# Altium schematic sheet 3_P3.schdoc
size 307 x 218 mm; Symbol: Sheet-Symbol_A4; Device: Sheet-Symbol_A4; @Project Name: Project Name; @Page Count: 3; @Update Date: 2021.11.05; @Create Date: 2024-11-23; @Schematic Name: Schematic Name; @Page No: 1; @Page Name: P1; Company: EasyEDA.com; Version: V1.0; Page Size: A4; @Create Time: 4:43:57 PM; @Update Time: 1:48:45 AM; Title Block Position: 3; Width: 1170; Height: 825; Region Start: 1; X Region Count: 6; Y Region Count: 4; Blade Width: 10; @Board Name: PENTASLAM
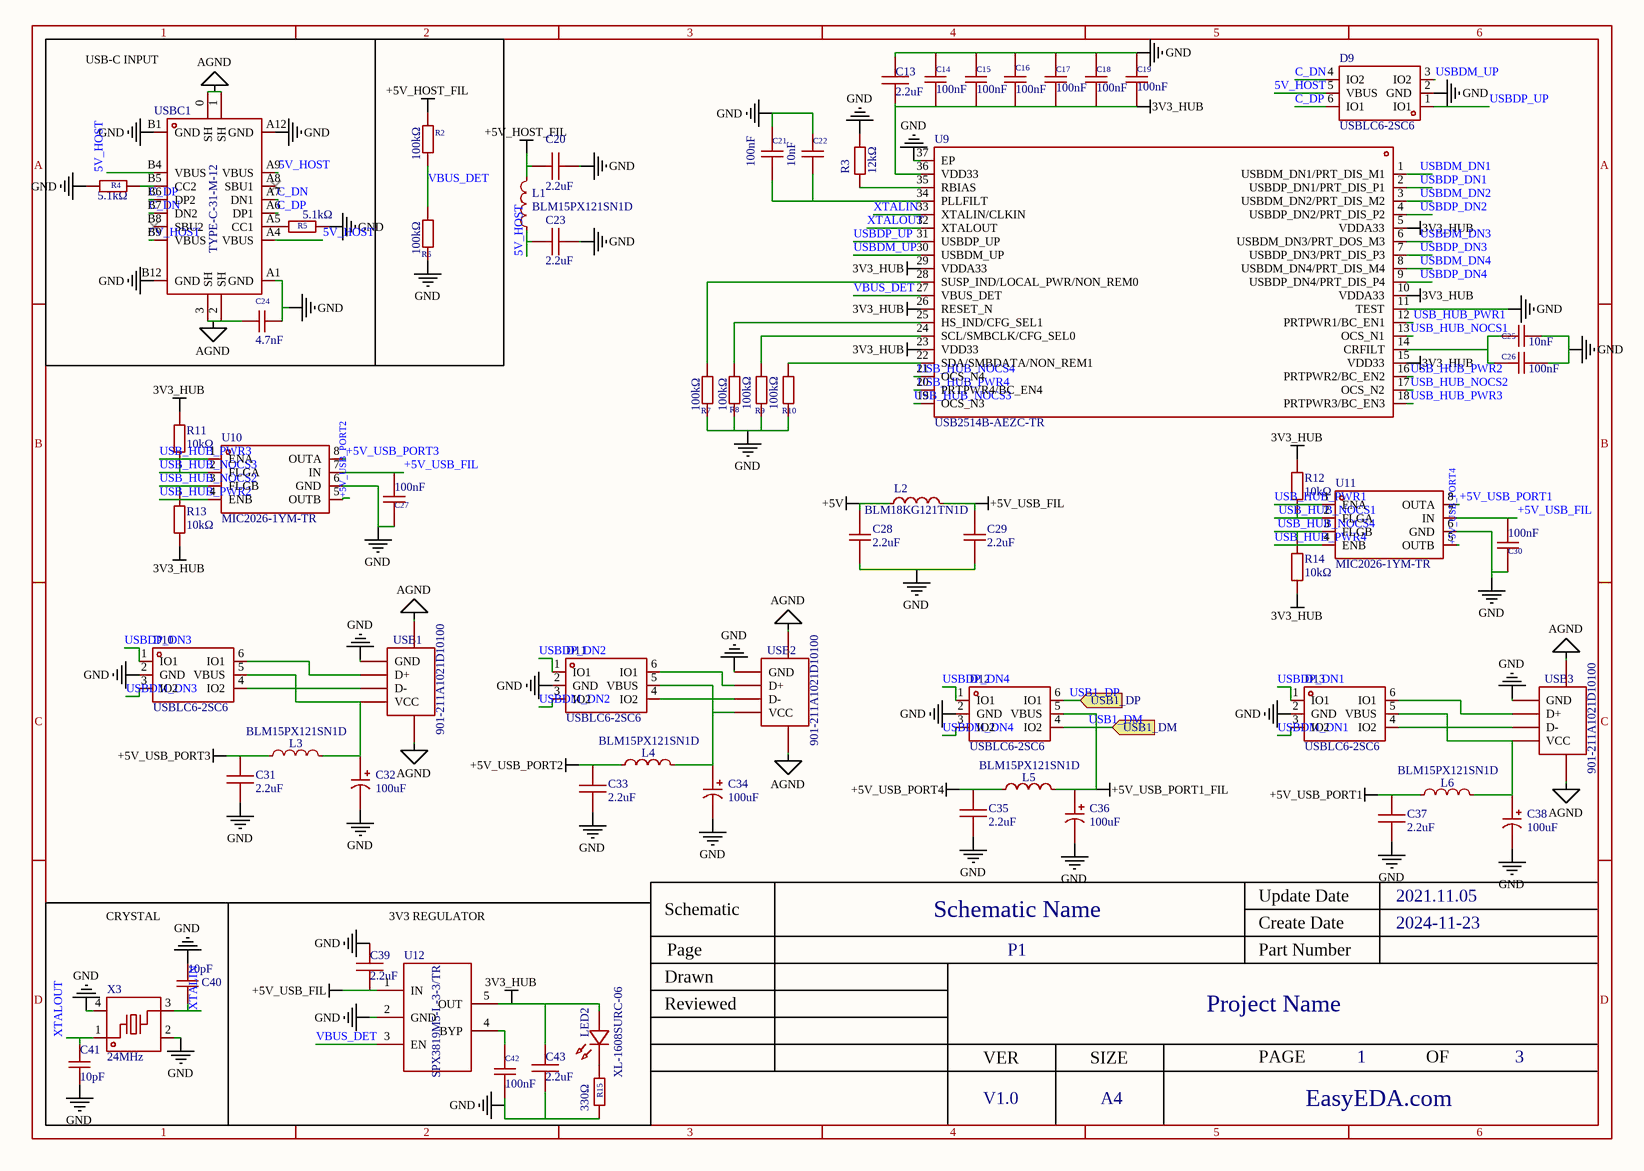
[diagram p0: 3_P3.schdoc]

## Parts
C13  2.2uF  [C0402]
C14  100nF  [C0402]
C15  100nF  [C0402]
C16  100nF  [C0402]
C17  100nF  [C0402]
C18  100nF  [C0402]
C19  100nF  [C0402]
C20  2.2uF  [C0402]
C21  100nF  [C0402]
C22  10nF  [C0402]
C23  2.2uF  [C0402]
C24  4.7nF  [C0402]
C25  10nF  [C0402]
C26  100nF  [C0402]
C27  100nF  [C0402]
C28  2.2uF  [C0402]
C29  2.2uF  [C0402]
C30  100nF  [C0402]
C31  2.2uF  [C0402]
C32  100uF  [CAP-SMD_BD5.0-L5.3-W5.3-LS6.3-FD]
C33  2.2uF  [C0402]
C34  100uF  [CAP-SMD_BD5.0-L5.3-W5.3-LS6.3-FD]
C35  2.2uF  [C0402]
C36  100uF  [CAP-SMD_BD5.0-L5.3-W5.3-LS6.3-FD]
C37  2.2uF  [C0402]
C38  100uF  [CAP-SMD_BD5.0-L5.3-W5.3-LS6.3-FD]
C39  2.2uF  [C0402]
C40  10pF  [C0402]
C41  10pF  [C0402]
C42  100nF  [C0402]
C43  2.2uF  [C0402]
D9  USBLC6-2SC6  [SOT-23-6_L2.9-W1.6-P0.95-LS2.8-BL]
D10  USBLC6-2SC6  [SOT-23-6_L2.9-W1.6-P0.95-LS2.8-BL]
D11  USBLC6-2SC6  [SOT-23-6_L2.9-W1.6-P0.95-LS2.8-BL]
D12  USBLC6-2SC6  [SOT-23-6_L2.9-W1.6-P0.95-LS2.8-BL]
D13  USBLC6-2SC6  [SOT-23-6_L2.9-W1.6-P0.95-LS2.8-BL]
L1  BLM15PX121SN1D  [L0402]
L2  BLM18KG121TN1D  [L0603]
L3  BLM15PX121SN1D  [L0402]
L4  BLM15PX121SN1D  [L0402]
L5  BLM15PX121SN1D  [L0402]
L6  BLM15PX121SN1D  [L0402]
LED2  XL-1608SURC-06  [LED0603-RD_RED]
R2  100kΩ  [R0603]
R3  12kΩ  [R0402]
R4  5.1kΩ  [R0402]
R5  5.1kΩ  [R0402]
R6  100kΩ  [R0603]
R7  100kΩ  [R0603]
R8  100kΩ  [R0603]
R9  100kΩ  [R0603]
R10  100kΩ  [R0603]
R11  10kΩ  [R0402]
R12  10kΩ  [R0402]
R13  10kΩ  [R0402]
R14  10kΩ  [R0402]
R15  330Ω  [R0402]
U9  USB2514B-AEZC-TR  [VQFN-36_L6.0-W6.0-P0.50-BL-EP]
U10  MIC2026-1YM-TR  [SOIC-8_L4.9-W3.9-P1.27-LS6.0-BL]
U11  MIC2026-1YM-TR  [SOIC-8_L4.9-W3.9-P1.27-LS6.0-BL]
U12  SPX3819M5-L-3-3/TR  [SOT-23-5_L3.0-W1.7-P0.95-LS2.8-BL]
USB1  901-211A1021D10100  [USB-A-TH_USB-M-1_C2346]
USB2  901-211A1021D10100  [USB-A-TH_USB-M-1_C2346]
USB3  901-211A1021D10100  [USB-A-TH_USB-M-1_C2346]
USBC1  TYPE-C-31-M-12  [USB-C_SMD-TYPE-C-31-M-12]
X3  24MHz  [CRYSTAL-SMD_4P-L2.0-W1.6-BL-A]

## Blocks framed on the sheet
USB-C INPUT: C24 R4 R5 USBC1
CRYSTAL: C40 C41 X3
3V3 REGULATOR: C39 C42 C43 LED2 R15 U12

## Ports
USB1_DM (in), USB1_DP (in)

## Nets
3V3_HUB: C13.2 C14.1 C15.1 C16.1 C17.1 C18.1 C19.2 C43.2 LED2.2(A) R11.2 R12.2 R13.1 R14.1 U9.5(VDDA33) U9.10(VDDA33) U9.15(VDD33) U9.23(VDD33) U9.26(RESET_N) U9.29(VDDA33) U9.36(VDD33) U12.5(OUT)
+5V: C28.1 L2.1
+5V_HOST_FIL: C20.2 L1.2 R2.2
+5V_USB_FIL: C27.2 C29.1 C30.2 C39.1 L2.2 U10.7(IN) U11.7(IN) U12.1(IN)
+5V_USB_PORT1: C37.2 L6.1 U11.8(OUTA)
+5V_USB_PORT1_FIL: C36.1 D12.5(VBUS) L5.2
+5V_USB_PORT2: C33.2 L4.1 U10.5(OUTB)
+5V_USB_PORT3: C31.2 L3.1 U10.8(OUTA)
+5V_USB_PORT4: C35.2 L5.1 U11.5(OUTB)
AGND: C24.1 USB1.0 USB2.0 USB3.0 USBC1.0(SH) USBC1.1(SH) USBC1.2(SH) USBC1.3(SH)
GND: C13.1 C14.2 C15.2 C16.2 C17.2 C18.2 C19.1 C20.1 C21.2 C22.2 C23.1 C24.2 C25.2 C26.2 C27.1 C28.2 C29.2 C30.1 C31.1 C32.2 C33.1 C34.2 C35.1 C36.2 C37.1 C38.2 C39.2 C40.2 C41.2 C42.1 C43.1 D9.2(GND) D10.2(GND) D11.2(GND) D12.2(GND) D13.2(GND) R3.2 R4.1 R5.2 R6.1 R7.1 R8.1 R9.1 R10.1 R15.1 U9.11(TEST) U9.37(EP) U10.6(GND) U11.6(GND) U12.2(GND) USB1.4(GND) USB2.4(GND) USB3.4(GND) USBC1.A1(GND) USBC1.A12(GND) USBC1.B1(GND) USBC1.B12(GND) X3.2(GND) X3.4(GND)
5V_HOST: C23.2 D9.5(VBUS) L1.1 USBC1.A4(VBUS) USBC1.A9(VBUS) USBC1.B4(VBUS) USBC1.B9(VBUS)
C_DN: D9.4(IO2) USBC1.A7(DN1) USBC1.B7(DN2)
C_DP: D9.6(IO1) USBC1.A6(DP1) USBC1.B6(DP2)
USB1_DM: D12.4(IO2) ; port USB1_DM
USB1_DP: D12.6(IO1) ; port USB1_DP
USB_HUB_NOCS1: R12.1 U9.13(OCS_N1) U11.2(FLGA)
USB_HUB_NOCS2: R13.2 U9.17(OCS_N2) U10.3(FLGB)
USB_HUB_NOCS3: R11.1 U9.19(OCS_N3) U10.2(FLGA)
USB_HUB_NOCS4: R14.2 U9.21(OCS_N4) U11.3(FLGB)
USB_HUB_PWR1: U9.12(PRTPWR1/BC_EN1) U11.1(ENA)
USB_HUB_PWR2: U9.16(PRTPWR2/BC_EN2) U10.4(ENB)
USB_HUB_PWR3: U9.18(PRTPWR3/BC_EN3) U10.1(ENA)
USB_HUB_PWR4: U9.20(PRTPWR4/BC_EN4) U11.4(ENB)
USBDM_DN1: D13.3(IO2) U9.1(USBDM_DN1/PRT_DIS_M1)
USBDM_DN2: D11.3(IO2) U9.3(USBDM_DN2/PRT_DIS_M2)
USBDM_DN3: D10.3(IO2) U9.6(USBDM_DN3/PRT_DOS_M3)
USBDM_DN4: D12.3(IO2) U9.8(USBDM_DN4/PRT_DIS_M4)
USBDM_UP: D9.3(IO2) U9.30(USBDM_UP)
USBDP_DN1: D13.1(IO1) U9.2(USBDP_DN1/PRT_DIS_P1)
USBDP_DN2: D11.1(IO1) U9.4(USBDP_DN2/PRT_DIS_P2)
USBDP_DN3: D10.1(IO1) U9.7(USBDP_DN3/PRT_DIS_P3)
USBDP_DN4: D12.1(IO1) U9.9(USBDP_DN4/PRT_DIS_P4)
USBDP_UP: D9.1(IO1) U9.31(USBDP_UP)
VBUS_DET: R2.1 R6.2 U9.27(VBUS_DET) U12.3(EN)
XTALIN: C40.1 U9.33(XTALIN/CLKIN) X3.3
XTALOUT: C41.1 U9.32(XTALOUT) X3.1
NetC21_1: C21.1 C22.1 U9.34(PLLFILT)
NetC25_1: C25.1 C26.1 U9.14(CRFILT)
NetC32_1: C32.1 D10.5(VBUS) L3.2 USB1.1(VCC)
NetC34_1: C34.1 D11.5(VBUS) L4.2 USB2.1(VCC)
NetC38_1: C38.1 D13.5(VBUS) L6.2 USB3.1(VCC)
NetC42_2: C42.2 U12.4(BYP)
NetD10_4: D10.4(IO2) USB1.2(D-)
NetD10_6: D10.6(IO1) USB1.3(D+)
NetD11_4: D11.4(IO2) USB2.2(D-)
NetD11_6: D11.6(IO1) USB2.3(D+)
NetD13_4: D13.4(IO2) USB3.2(D-)
NetD13_6: D13.6(IO1) USB3.3(D+)
NetLED2_1: LED2.1(K) R15.2
NetR3_1: R3.1 U9.35(RBIAS)
NetR4_2: R4.2 USBC1.B5(CC2)
NetR5_1: R5.1 USBC1.A5(CC1)
NetR7_2: R7.2 U9.28(SUSP_IND/LOCAL_PWR/NON_REM0)
NetR8_2: R8.2 U9.25(HS_IND/CFG_SEL1)
NetR9_2: R9.2 U9.24(SCL/SMBCLK/CFG_SEL0)
NetR10_2: R10.2 U9.22(SDA/SMBDATA/NON_REM1)

Not connected (* = marked no-connect by the designer): USBC1 A8(SBU1)* B8(SBU2)*

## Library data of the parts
C13 C20 C23 C31 C33 C35 C37 C39 C43 = CL05A225MQ5NSNC: Manufacturer: SAMSUNG(三星); Add into BOM: yes; Tolerance: ±20%
C14-C19 C21 C26 C42 = CC0402KRX7R7BB104: Manufacturer: YAGEO(国巨); Add into BOM: yes; Tolerance: ±10%
C22 C25 = CC0402KRX7R9BB103: Manufacturer: YAGEO(国巨); Add into BOM: yes; Tolerance: ±10%
C24 = CC0402KRX7R9BB472: Manufacturer: YAGEO(国巨); Add into BOM: yes; Tolerance: ±10%
C27 C30 = CT41G-0402-2X1-16V-0.1μF-K(N): Manufacturer: TORCH(火炬); Add into BOM: yes; Tolerance: ±10%
C28 C29 = CL05A225KO5NQNC: Manufacturer: SAMSUNG(三星); Add into BOM: yes; Tolerance: ±10%
C32 C34 C36 C38 = RVT1C101M0505: Manufacturer: ROQANG(容强); Add into BOM: yes; Tolerance: ±20%; Ripple Current: 50mA@120Hz; Lifetime @ Temp: 2000hrs@105℃
C40 C41 = 0402CG100J500NT: Manufacturer: FH(风华); Add into BOM: yes; Tolerance: ±5%
D9-D13 = USBLC6-2SC6_C2827654: Manufacturer: TECH PUBLIC(台舟); Add into BOM: yes; polarity: Unidirectional; Reverse Stand-Off Voltage (Vrwm): 5V; Maximum Clamping Voltage: 12V; Peak Pulse Current (Ipp): 6A; Peak Pulse Power Dissipation (Ppp): 150W; Breakdown Voltage: 6V; Reverse Leakage Current (Ir): 80nA; Number of Lines: Dual channel; level of protection: IEC 61000-4-2; Type: ESD
L1 L3-L6 = BLM15PX121SN1D: Manufacturer: muRata(村田); Add into BOM: yes; Impedance @ Frequency: 120Ω@100MHz; Tolerance: ±25%; DC Resistance: 55mΩ; Current Rating: 2A; Circuits: 1
L2 = BLM18KG121TN1D: Manufacturer: muRata(村田); Add into BOM: yes; Impedance @ Frequency: 120Ω@100MHz; Tolerance: ±25%; DC Resistance: 30mΩ; Current Rating: 3A; Circuits: 1
LED2 = XL-1608SURC-06: Manufacturer: XINGLIGHT(成兴光); Add into BOM: yes; Emitted Color: Red; Power Dissipation: 55mW; Forward Current: 25mA; Dominant Wavelength: 617nm~621nm; Peak Wavelength: 623nm; Lens Color: 无色透明透镜; Viewing Angle: 120°; Mounting Sytle: Positive post
R2 R6-R10 = RC0603FR-07100KL: Manufacturer: YAGEO(国巨); Add into BOM: yes; Tolerance: ±1%; Temperature Coefficient: ±100ppm/℃
R3 = RC0402FR-0712KL: Manufacturer: YAGEO(国巨); Add into BOM: yes; Tolerance: ±1%; Temperature Coefficient: ±100ppm/℃
R4 R5 = RMC04025.1K1%N: Manufacturer: Tyohm(幸亚电阻); Add into BOM: yes; Tolerance: ±1%
R11-R14 = RC0402FR-0710KL: Manufacturer: YAGEO(国巨); Add into BOM: yes; Tolerance: ±1%; Temperature Coefficient: ±100ppm/℃
R15 = 0402WGF3300TCE: Manufacturer: UNI-ROYAL(厚声); Add into BOM: yes; Tolerance: ±1%; Temperature Coefficient: ±100ppm/℃
U9 = USB2514B-AEZC-TR: Manufacturer: MICROCHIP(美国微芯); Add into BOM: yes; Protocol: USB 2.0; Supply Voltage: 3.3V
U10 U11 = MIC2026-1YM-TR: Manufacturer: MICROCHIP(美国微芯); Add into BOM: yes; Number of Outputs: 2; Output Current: 1.25A; Input Voltage: 2.7V~5.5V; Resistor On-State: 90mΩ
U12 = SPX3819M5-L-3-3/TR: Manufacturer: MaxLinear(迈凌); Add into BOM: yes; Output Type: Fixed; Maximum Input Voltage: 16V; Output Voltage: 3.3V; Output Current: 500mA; Power Supply Rejection Ratio (PSRR): 70dB; Dropout Voltage: 700mV@(500mA); standby current: 8uA; Output Polarity: Positive electrode; Number of Outputs: 1
USB1-USB3 = 901-211A1021D10100: Manufacturer: 精拓金; Symbol: USB A/F 90° Outside the buckle straight foot; Add into BOM: yes; Connector Type: Type-A; Gender: Female; Number of Ports: 1; Number of Contacts: 4P
USBC1 = TYPE-C-31-M-12: Manufacturer: 韩国韩荣; Add into BOM: yes; Connector Type: Type-C; Gender: Female; Number of Contacts: 16P; Number of Ports: 1; Current Rating - Power (Max): 5A
X3 = XL7EL89CKI-111YLC-24M: Manufacturer: YXC(扬兴晶振); Add into BOM: yes; Crystal Type: Surface Mount Crystal; Normal temperature Frequency Tolerance: ±10ppm; Frequency Stability(Full temperature range): ±20ppm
